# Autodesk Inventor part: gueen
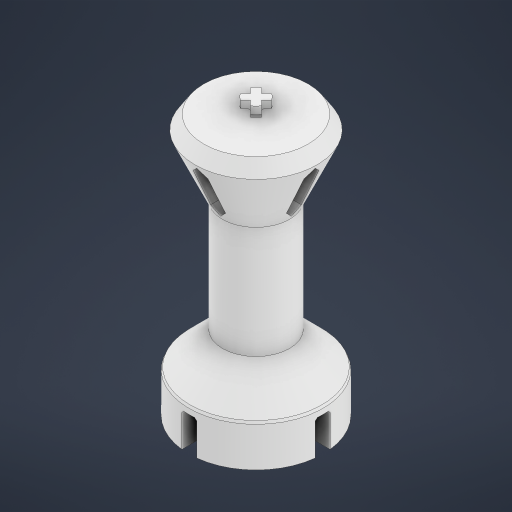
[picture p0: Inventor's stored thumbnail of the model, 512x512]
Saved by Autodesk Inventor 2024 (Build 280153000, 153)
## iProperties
Created: 2025-07
Part Number: gueen
Material: ABS Plastic
Document SubType Name: Modeling
Designer: acer
Density: 1.06 g/cm^3
Appearance: Smooth - White
Author: acer
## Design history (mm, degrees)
sketch "Sketch1"
  geometry: L1 (-18.281, -5.281)-(16.719, -5.281); L2 (-18.281, -5.281)-(-18.281, 3.719); L3 (-18.281, 3.719)-(-12.781, 3.719); L4 (-12.781, 3.719)-(-8.281, -0.781); L5 (-8.281, -0.781)-(6.719, -0.781); L6 (6.719, -0.781)-(16.719, 3.719); L7 (16.719, 3.719)-(16.719, -5.281); 1 further point
  constraints: 14 end point, 2 vertical, 1 horizontal, 1 parallel, 1 perpendicular, 1 point on line
  dimensions: "d0" = 35 distance of L1.start L1.end; "d1" = 9 distance of L1.start L2.end; "d2" = 5.5 distance of L2.end L3.end; "d3" = 135 deg angle of L3 L4; "d4" = 15 distance of L4.end L5.end
revolve "Revolution1" sketch "Sketch1" stored, may be unused: angle "d5" = 90 deg
chamfer "Chamfer1" distance "d6" = 0.2; stored, may be unused: second distance "d7" = 2, angle "d8" = 45 deg
chamfer "Chamfer2" distance "d9" = 2; stored, may be unused: second distance "d10" = 2, angle "d11" = 45 deg
sketch "Sketch2"
  geometry: L1 (14.895, -13.461)-(14.895, 2.898) reference; L2 (-1.458, -4.281)-(14.895, -4.281); L3 (14.895, -4.281)-(14.895, -6.281); L4 (14.895, -6.281)-(-1.458, -6.281); L5 (-1.458, -6.281)-(-1.458, -4.281); L6 (6.719, -9.781)-(6.719, -0.781) reference; L7 (-1.458, -4.281)-(14.895, -6.281); L8 (14.895, -4.281)-(-1.458, -6.281); L9 (14.895, -5.281)-(14.895, -3.781); L10 (14.895, -5.281)-(16.395, -5.281); L11 (6.719, -5.281)-(6.719, -3.781); L12 (6.719, -5.281)-(8.219, -5.281); L13 (14.895, -5.281)-(13.395, -5.281); L14 (14.395, -5.281)-(13.395, -6.281); L15 (14.395, -5.281)-(13.395, -4.281); L16 (7.219, -5.281)-(8.219, -6.281); L17 (7.219, -5.281)-(8.219, -4.281); A1 r 1 centre (8.219, -5.281) between (7.219, -5.281) and (8.219, -6.281); A2 r 1 centre (13.395, -5.281) between (14.395, -5.281) and (13.395, -6.281); 1 further point
  constraints: 30 end point, 7 point on line, 6 point on circle, 4 horizontal, 4 midpoint, 3 perpendicular, 2 centre point, 2 coincident, 2 parallel, 2 vertical
  dimensions: "d12" = 2 distance of L2.end L3.end; "d13" = 1.5 distance of L9.start L9.end; "d14" = 90 deg angle of L10 L9 (derived); "d15" = 1.5 distance of L11.start L11.end; "d16" = 90 deg angle of L12 L11 (derived); "d17" = 2 diameter of A1; "d18" = 1.5 distance of L9.start L13.end; "d19" = 2 diameter of A2
extrude "Extrusion1" cut sketch "Sketch2" stored distance "d20" = 20.25; taper "d21" = 0 deg
workplane "Work Plane1"
sketch "Sketch4"
  geometry: L1 (8.179, 14.895)-(-8.179, 14.895) reference; L2 (-1, -1.458)-(1, -1.458); L3 (1, -1.458)-(1, 14.895); L4 (1, 14.895)-(-1, 14.895); L5 (-1, 14.895)-(-1, -1.458); L6 (4.5, 6.719)-(-4.5, 6.719) reference; L7 (-1, -1.458)-(1, 14.895); L8 (1, -1.458)-(-1, 14.895); L9 (0, 6.719)-(0, 8.219); L10 (0, 6.719)-(1.5, 6.719); L11 (0, 14.895)-(0, 13.395); L12 (-7.437, 13.395)-(7.437, 13.395) reference; L13 (0, 7.219)-(1, 8.219); L14 (0, 7.219)-(-1, 8.219); L15 (-7.954, 14.395)-(7.954, 14.395) reference; L16 (0, 14.395)-(-1, 13.395); L17 (0, 14.395)-(1, 13.395); A1 r 1 centre (0, 13.395) between (-1, 13.395) and (1, 13.395); A2 r 1 centre (0, 8.219) between (0, 7.219) and (1, 8.219); 3 further points
  constraints: 26 end point, 6 midpoint, 6 point on line, 5 point on circle, 2 centre point, 2 coincident, 2 horizontal, 2 parallel, 2 perpendicular, 1 vertical
  dimensions: "d30" = 2 distance of L4.end L3.end; "d31" = 1.5 distance of L9.start L9.end; "d32" = 90 deg angle of L10 L9 (derived); "d33" = 1.5 distance of L11.start L11.end (derived); "d34" = 2 diameter of A1; "d35" = 2 diameter of A2
extrude "Extrusion2" cut sketch "Sketch4" stored distance "d36" = 50; taper "d37" = 0 deg
sketch "Sketch5"
  geometry: L1 (1, 1)-(7.437, 1) reference; L2 (0, 0)-(4.725, 0) reference; L3 (0, 0)-(0, -4.725) reference; L4 (0, -0.75)-(-0.75, 0); L5 (-4.725, 0)-(0, 0) reference; L6 (-0.75, 0)-(0, 0.75); L7 (0, 0.75)-(0.75, 0); L8 (0.75, 0)-(0, -0.75); A1 r 0.75 centre (0, 0) between (0, -0.75) and (-0.75, 0); 1 further point
  constraints: 8 end point, 4 point on circle, 3 point on line, 1 centre point, 1 coincident, 1 perpendicular
  dimensions: "d40" = 1.5 diameter of A1
extrude "Extrusion3" join sketch "Sketch5" distance "d41" = 2; taper "d42" = 0 deg
sketch "Sketch6" dims "d43" = 3.1
  geometry: L1 (-4.725, 0)-(0, 0) reference; L2 (0, -0.75)-(-0.75, 0) reference; L3 (-0.375, -0.375)-(-1.405, 0.655); L4 (-0.375, -0.375)-(0.655, -1.405); L5 (0, 0.75)-(0.75, 0) reference; L6 (0.375, 0.375)-(1.405, -0.655); L7 (1.405, -0.655)-(-0.655, 1.405); L8 (0.75, 0)-(0, -0.75) reference; L9 (0.375, -0.375)-(1.405, 0.655); L10 (1.405, 0.655)-(-0.655, -1.405); L11 (-0.75, 0)-(0, 0.75) reference; L12 (-0.375, 0.375)-(0.655, 1.405); L13 (0.655, 1.405)-(-1.405, -0.655); 5 further points
  constraints: 16 end point, 4 collinear, 4 midpoint, 4 point on line, 10 other
extrude "Extrusion4" join sketch "Sketch6" distance "d44" = 1; taper "d45" = 0 deg
chamfer "Chamfer3" distance "d46" = 0.2; stored, may be unused: second distance "d47" = 2, angle "d48" = 45 deg
sketch "Sketch7"
  geometry: L1 (9, -12.981)-(-9, -12.981) reference; L2 (-1, -23.581)-(1, -23.581); L3 (1, -23.581)-(1, -12.981); L4 (1, -12.981)-(-1, -12.981); L5 (-1, -12.981)-(-1, -23.581); L6 (9, -18.281)-(-9, -18.281) reference; L7 (-1, -23.581)-(1, -12.981); L8 (1, -23.581)-(-1, -12.981); L9 (0, -12.981)-(0, -13.981); L10 (0, -12.981)-(-1, -13.981); L11 (0, -12.981)-(1, -13.981); A1 r 1 centre (0, -13.981) between (0, -12.981) and (-1, -13.981); 4 further points
  constraints: 18 end point, 4 midpoint, 3 point on circle, 3 point on line, 2 parallel, 1 centre point, 1 coincident, 1 horizontal, 1 perpendicular, 1 vertical
  dimensions: "d49" = 2 distance of L4.end L3.end; "d50" = 1 distance of L9.start L9.end
extrude "Extrusion5" cut sketch "Sketch7" stored distance "d51" = 32; taper "d52" = 0 deg
chamfer "Chamfer4" distance "d53" = 1; stored, may be unused: second distance "d54" = 2, angle "d55" = 45 deg
sketch "Sketch8"
  geometry: L1 (-12.981, -14.281)-(-12.981, 3.719) reference; L2 (-23.581, -4.281)-(-12.981, -4.281); L3 (-12.981, -4.281)-(-12.981, -6.281); L4 (-12.981, -6.281)-(-23.581, -6.281); L5 (-23.581, -6.281)-(-23.581, -4.281); L6 (-18.281, -14.226)-(-18.281, 3.663) reference; L7 (-23.581, -4.281)-(-12.981, -6.281); L8 (-12.981, -4.281)-(-23.581, -6.281); L9 (-12.981, -5.281)-(-13.981, -5.281); L10 (-12.981, -5.281)-(-13.981, -4.281); L11 (-12.981, -5.281)-(-13.981, -6.281); L12 (-13.981, -14.226)-(-13.981, 3.663) reference; A1 r 1 centre (-13.981, -5.281) between (-12.981, -5.281) and (-13.981, -4.281); 5 further points
  constraints: 18 end point, 4 midpoint, 3 point on circle, 3 point on line, 2 horizontal, 2 parallel, 1 centre point, 1 coincident, 1 perpendicular
  dimensions: "d56" = 2 distance of L2.end L3.end; "d57" = 1 distance of L9.start L9.end
extrude "Extrusion6" cut sketch "Sketch8" stored distance "d58" = 32; taper "d59" = 0 deg
chamfer "Chamfer5" distance "d60" = 1; stored, may be unused: second distance "d61" = 2, angle "d62" = 45 deg
body "Solid1"
other parameters: "d29" = 5.25
